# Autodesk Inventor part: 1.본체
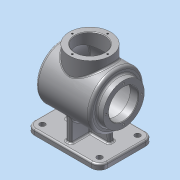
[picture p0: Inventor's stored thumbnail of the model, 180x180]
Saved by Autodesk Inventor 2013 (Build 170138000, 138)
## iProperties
Created: 2016-09
Part Number: 1.본체
Material: 알루미늄 6061
Document SubType Name: Modeling
Designer: Administrator
Density: 2.71 g/cm^3
Mass: 972.44 g
Surface Area: 1283.07 cm^2
Volume: 358.834 cm^3
Author: Administrator
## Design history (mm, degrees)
sketch "스케치1"
  geometry: L1 (-52.5, 50)-(52.5, 50); L2 (67.5, 35)-(67.5, -35); L3 (52.5, -50)-(-52.5, -50); L4 (-67.5, -35)-(-67.5, 35); A1 r 15 centre (-52.5, 35) between (-52.5, 50) and (-67.5, 35); A2 r 15 centre (-52.5, -35) between (-67.5, -35) and (-52.5, -50); A3 r 15 centre (52.5, -35) between (52.5, -50) and (67.5, -35); A4 r 15 centre (52.5, 35) between (67.5, 35) and (52.5, 50); 5 further points
  constraints: 8 end point, 8 point on circle, 8 tangent, 4 centre point, 4 point on line, 3 equal radius, 2 midpoint, 2 parallel, 1 horizontal, 1 horizontal alignment, 1 perpendicular, 1 vertical alignment
  dimensions: "d0" = 135 distance of point (-67.5, 50) point (67.5, 50); "d2" = 100 distance between parallel lines of L3 L1; "d3" = 15 radius of A1
extrude "돌출1" new body sketch "스케치1" distance "d4" = 10; taper "d5" = 0 deg
sketch "스케치2"
  geometry: L1 (-50, 82)-(60, 82); L2 (-52.5, 0)-(-67.5, 0) reference; L3 (-50, 82)-(-50, 132); L4 (-50, 132)-(48.562, 132); A1 r 115 centre (-55, 82) between (60, 82) and (48.562, 132); 1 further point
  constraints: 6 end point, 2 perpendicular, 2 point on circle, 1 centre point, 1 horizontal, 1 horizontal alignment
  dimensions: "d6" = 82 distance between parallel lines of L2 L1; "d7" = 110 distance of L1.start L1.end; "d8" = 50 horizontal distance of point (0, 0) L1.start; "d9" = 115 radius of A1; "d10" = 100 diameter of L4 L1
revolve "회전1" sketch "스케치2" stored, may be unused: angle "d11" = 90 deg
node "작업 평면1"
sketch "스케치3"
  geometry: L1 (35, 0)-(-35, 0) reference; 2 further points
  constraints: 1 vertical alignment, 1 other
  dimensions: "d120" = 82 distance from line of point (0, 82) L1
feature "엠보싱1" sketch "스케치3" dims "d0" = 135, "d2" = 100, "d3" = 15, "d6" = 82, "d7" = 110, "d8" = 50, "d9" = 115, "d10" = 100, "d13" = 0.5, "d14" = 0
sketch "스케치4"
  geometry: L1 (52.5, 10)-(-52.5, 10) reference; L2 (-40, 10)-(-34.51, 72.751); L3 (-34.51, 72.751)-(34.51, 72.751); L4 (34.51, 72.751)-(40, 10); 2 further points
  constraints: 6 end point, 2 point on line, 1 equal length, 1 midpoint, 1 parallel, 1 vertical alignment
  dimensions: "d15" = 95 deg angle of L1 L4; "d16" = 40 horizontal distance of point (0, 0) L2.start; "d17" = 62.75078 distance between parallel lines of L1 L3
extrude "돌출2" join sketch "스케치4" stored distance "d18" = 10; taper "d19" = 0 deg
sketch "스케치5"
  geometry: L1 (35, 10)-(-35, 10) reference; L2 (-40, 10)-(40, 10); L3 (40, 10)-(40, 73.198); L4 (40, 73.198)-(-40, 73.198); L5 (-40, 73.198)-(-40, 10); 2 further points
  constraints: 8 end point, 2 parallel, 1 horizontal, 1 midpoint, 1 perpendicular, 1 point on line, 1 vertical alignment
  dimensions: "d20" = 80 distance of L3.end L4.end; "d22" = 63.19791 distance between parallel lines of L1 L4
extrude "돌출3" join sketch "스케치5" stored distance "d23" = 10; taper "d24" = 0 deg
sketch "스케치6"
  geometry: C1 r 50 at (0, 0) reference; C2 r 38 at (0, 0); 1 further point
  constraints: 1 centre point, 1 coincident
  dimensions: "d25" = 76 diameter of C2
extrude "돌출4" join sketch "스케치6" distance "d26" = 12; taper "d27" = 0 deg
node "작업 평면2"
sketch "스케치8"
  geometry: C1 r 38 at (0, 0); 1 further point
  constraints: 1 centre point, 1 coincident
  dimensions: "d34" = 76 diameter of C1
extrude "돌출5" join sketch "스케치8" distance "d36" = 50; taper "d37" = 0 deg
sketch "스케치9"
  geometry: L1 (-62, 120)-(-62, 44) reference; L2 (-50, 44)-(-50, 120) reference; L3 (-62, 82)-(114.804, 82); L4 (-62, 82)-(-62, 109); L5 (-62, 109)-(-47, 109); L6 (-47, 109)-(-47, 129); L7 (-47, 129)-(46.661, 129); L8 (-50, 132)-(48.562, 132) reference; A1 r 115 centre (-55, 82) between (48.562, 32) and (48.562, 132) reference; A2 r 112 centre (-55, 82) between (57, 82) and (46.661, 129); 1 further point
  constraints: 10 end point, 3 perpendicular, 2 point on circle, 2 point on line, 1 centre point, 1 midpoint, 1 parallel
  dimensions: "d38" = 3 distance between parallel lines of L7 L8; "d39" = 15 distance of L4.end L5.end; "d40" = 3 radial gap between concentric circles of A1 A2; "d41" = 54 diameter of L5 L3
revolve "회전3" sketch "스케치9" stored, may be unused: angle "d42" = 90 deg
hole "구멍1" diameter "d45" = 54; stored, may be unused: countersink angle "d49" = 90 deg, drill point angle "d51" = 0 deg; dims "d43" = 10, "d44" = 10, "d46" = 6, "d47" = 4, "d48" = 2, "d50" = 50
sketch "스케치10" dims "d52" = 65
  geometry: C1 r 38 at (0, 0) reference; 3 further points
  constraints: 2 horizontal alignment, 1 coincident, 2 other
hole "구멍2" sketch "스케치10" at (-32.5, 0) diameter "d53" = 3.242; stored, may be unused: countersink angle "d57" = 90 deg, drill point angle "d59" = 118 deg; dims "d54" = 8, "d55" = 4, "d56" = 2, "d58" = 10
sketch "스케치11" dims "d63" = 65
  geometry: 3 further points
  constraints: 2 vertical alignment, 1 coincident, 2 other
hole "구멍3" sketch "스케치11" at (0, 32.5) diameter "d64" = 3.242; stored, may be unused: countersink angle "d68" = 90 deg, drill point angle "d70" = 118 deg; dims "d65" = 8, "d66" = 4, "d67" = 2, "d69" = 10
hole "구멍4" diameter "d76" = 10; stored, may be unused: countersink angle "d80" = 90 deg, drill point angle "d82" = 0 deg; dims "d74" = 10, "d75" = 10, "d77" = 8, "d78" = 4, "d79" = 2, "d81" = 10
hole "구멍5" diameter "d85" = 10; stored, may be unused: countersink angle "d89" = 90 deg, drill point angle "d91" = 0 deg; dims "d83" = 10, "d84" = 10, "d86" = 8, "d87" = 4, "d88" = 2, "d90" = 10
hole "구멍6" diameter "d94" = 10; stored, may be unused: countersink angle "d98" = 90 deg, drill point angle "d100" = 0 deg; dims "d92" = 10, "d93" = 10, "d95" = 8, "d96" = 4, "d97" = 2, "d99" = 10
hole "구멍7" diameter "d103" = 10; stored, may be unused: countersink angle "d107" = 90 deg, drill point angle "d109" = 0 deg; dims "d101" = 10, "d102" = 10, "d104" = 8, "d105" = 4, "d106" = 2, "d108" = 10
fillet "모깎기1" dims "d110" = 5
fillet "모깎기2" dims "d111" = 3
fillet "모깎기3" dims "d112" = 2
chamfer "모따기1" distance "d113" = 1; stored, may be unused: second distance "d114" = 2, angle "d115" = 45 deg
fillet "모깎기4" dims "d116" = 3
fillet "모깎기5" dims "d117" = 3
fillet "모깎기6" dims "d118" = 3
fillet "모깎기7" dims "d119" = 3
node "솔리드1"
pattern_circular "원형 패턴1" dims angle "d61" = 360 deg
pattern_circular "원형 패턴2" dims angle "d72" = 360 deg
node "투영된 루프1"
other parameters: "d12" = -28.5, "d33" = 147
